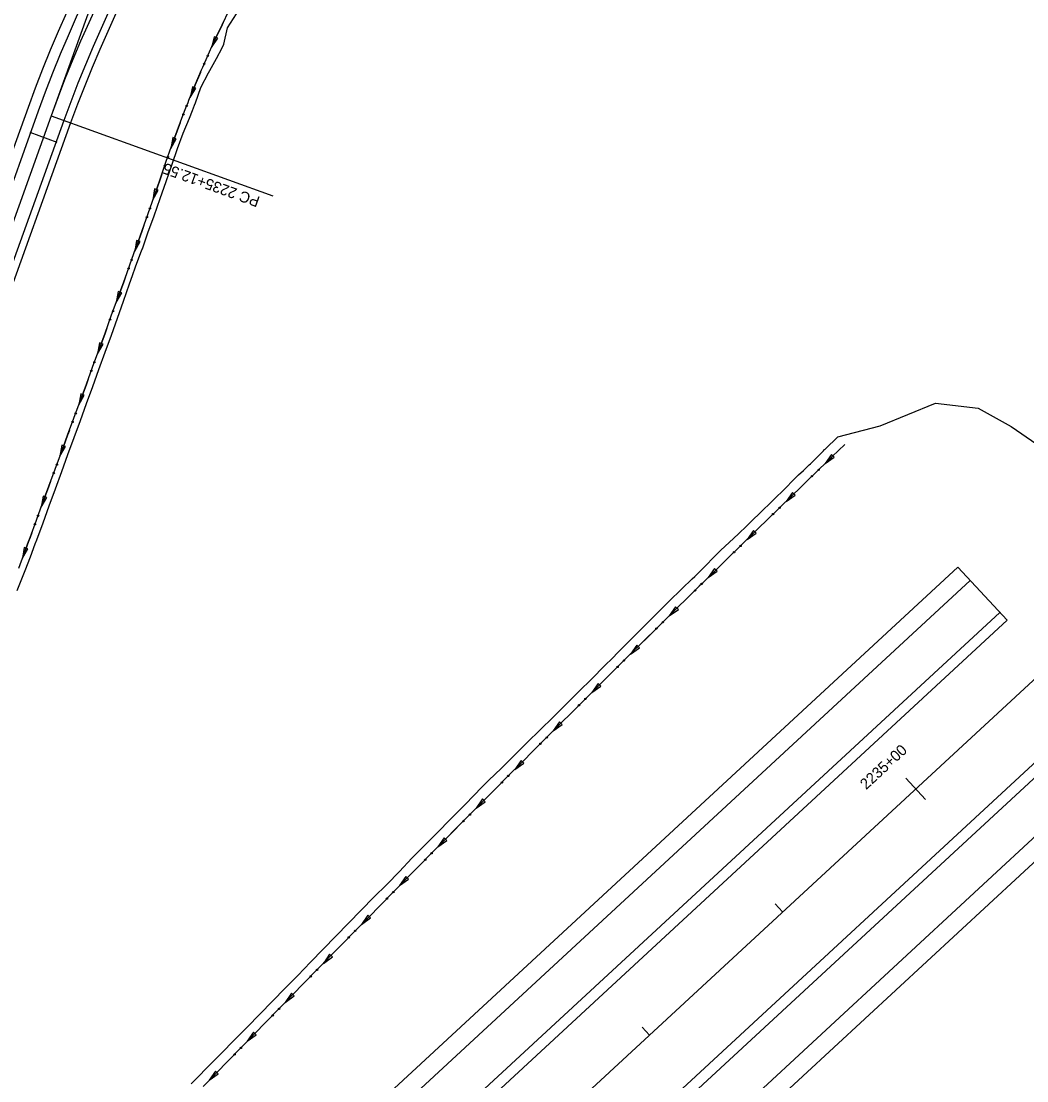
# Model space of a CAD drawing. Extents: x 1611108 to 1749517, y 619561 to 797725.
# Drawn here: x 1727502 to 1728056, y 772043 to 772627 of the extents above; entities that cross this region are included whole.
import ezdxf

# ---------------------------------------------------------------- set-up
doc = ezdxf.new("R2010")
doc.units = 0
for name, color, linetype in [('R_Ditch', 7, 'Continuous'), ('R_Horz Alg', 7, 'Continuous'), ('R_Horz Alg Annot', 7, 'Continuous'), ('R_Horz Alg Stationing', 7, 'Continuous'), ('R_Proposed Const Limits', 7, 'Continuous'), ('R_Proposed Road', 7, 'Continuous')]:
    doc.layers.add(name, color=color, linetype=linetype)

msp = doc.modelspace()

# ---------------------------------------------------------------- linework, layer by layer
at = {"layer": 'R_Ditch'}
for p, q in [((1727608.03, 772618.77), (1727606.46, 772612.89)), ((1727606.46, 772612.89), (1727609.95, 772617.88)), ((1727609.95, 772617.88), (1727608.03, 772618.77)), ((1727595.97, 772591.21), (1727594.68, 772585.26)), ((1727594.68, 772585.26), (1727597.92, 772590.41)), ((1727597.92, 772590.41), (1727595.97, 772591.21)), ((1727585.09, 772563.17), (1727584.03, 772557.17)), ((1727584.03, 772557.17), (1727587.08, 772562.45)), ((1727587.08, 772562.45), (1727585.09, 772563.17)), ((1727575.12, 772534.82), (1727574.14, 772528.81)), ((1727574.14, 772528.81), (1727577.12, 772534.12)), ((1727577.12, 772534.12), (1727575.12, 772534.82)), ((1727565.16, 772506.49), (1727564.16, 772500.48)), ((1727567.15, 772505.78), (1727565.16, 772506.49)), ((1727564.16, 772500.48), (1727567.15, 772505.78)), ((1727555, 772478.23), (1727553.95, 772472.23)), ((1727553.95, 772472.23), (1727556.99, 772477.51)), ((1727556.99, 772477.51), (1727555, 772478.23)), ((1727544.73, 772450.01), (1727543.66, 772444.01)), ((1727543.66, 772444.01), (1727546.71, 772449.28)), ((1727546.71, 772449.28), (1727544.73, 772450.01)), ((1727534.38, 772421.81), (1727533.3, 772415.81)), ((1727533.3, 772415.81), (1727536.36, 772421.08)), ((1727536.36, 772421.08), (1727534.38, 772421.81)), ((1727524.02, 772393.62), (1727522.94, 772387.62)), ((1727522.94, 772387.62), (1727526, 772392.89)), ((1727526, 772392.89), (1727524.02, 772393.62)), ((1727948.41, 772388.44), (1727944.83, 772383.5)), ((1727944.83, 772383.5), (1727949.88, 772386.92)), ((1727949.88, 772386.92), (1727948.41, 772388.44)), ((1727926.84, 772367.52), (1727923.28, 772362.58)), ((1727928.32, 772366.01), (1727926.84, 772367.52)), ((1727513.65, 772365.42), (1727512.58, 772359.42)), ((1727512.58, 772359.42), (1727515.64, 772364.69)), ((1727515.64, 772364.69), (1727513.65, 772365.42)), ((1727923.28, 772362.58), (1727928.32, 772366.01)), ((1727905.32, 772346.56), (1727901.77, 772341.61)), ((1727901.77, 772341.61), (1727906.8, 772345.05)), ((1727906.8, 772345.05), (1727905.32, 772346.56)), ((1727503.29, 772337.23), (1727502.22, 772331.23)), ((1727505.28, 772336.5), (1727503.29, 772337.23)), ((1727502.22, 772331.23), (1727505.28, 772336.5)), ((1727883.85, 772325.56), (1727880.31, 772320.6)), ((1727885.33, 772324.05), (1727883.85, 772325.56)), ((1727880.31, 772320.6), (1727885.33, 772324.05)), ((1727862.42, 772304.5), (1727858.89, 772299.54)), ((1727858.89, 772299.54), (1727863.9, 772303)), ((1727863.9, 772303), (1727862.42, 772304.5)), ((1727841.03, 772283.41), (1727837.52, 772278.43)), ((1727837.52, 772278.43), (1727842.52, 772281.9)), ((1727842.52, 772281.9), (1727841.03, 772283.41)), ((1727819.7, 772262.26), (1727816.19, 772257.28)), ((1727821.19, 772260.76), (1727819.7, 772262.26)), ((1727816.19, 772257.28), (1727821.19, 772260.76)), ((1727798.41, 772241.07), (1727794.91, 772236.08)), ((1727794.91, 772236.08), (1727799.9, 772239.57)), ((1727799.9, 772239.57), (1727798.41, 772241.07)), ((1727777.16, 772219.83), (1727773.67, 772214.84)), ((1727773.67, 772214.84), (1727778.66, 772218.34)), ((1727778.66, 772218.34), (1727777.16, 772219.83)), ((1727755.96, 772198.55), (1727752.48, 772193.55)), ((1727752.48, 772193.55), (1727757.46, 772197.06)), ((1727757.46, 772197.06), (1727755.96, 772198.55)), ((1727734.8, 772177.22), (1727731.34, 772172.21)), ((1727731.34, 772172.21), (1727736.31, 772175.73)), ((1727736.31, 772175.73), (1727734.8, 772177.22)), ((1727713.69, 772155.85), (1727710.24, 772150.83)), ((1727710.24, 772150.83), (1727715.2, 772154.36)), ((1727715.2, 772154.36), (1727713.69, 772155.85)), ((1727692.63, 772134.43), (1727689.19, 772129.4)), ((1727689.19, 772129.4), (1727694.14, 772132.95)), ((1727694.14, 772132.95), (1727692.63, 772134.43)), ((1727671.62, 772112.96), (1727668.18, 772107.93)), ((1727668.18, 772107.93), (1727673.13, 772111.49)), ((1727673.13, 772111.49), (1727671.62, 772112.96)), ((1727650.63, 772091.48), (1727647.19, 772086.45)), ((1727647.19, 772086.45), (1727652.14, 772090)), ((1727652.14, 772090), (1727650.63, 772091.48)), ((1727629.64, 772069.99), (1727626.2, 772064.96)), ((1727626.2, 772064.96), (1727631.15, 772068.51)), ((1727631.15, 772068.51), (1727629.64, 772069.99)), ((1727608.65, 772048.5), (1727605.21, 772043.47)), ((1727605.21, 772043.47), (1727610.16, 772047.02)), ((1727610.16, 772047.02), (1727608.65, 772048.5))]:
    msp.add_line(p, q, dxfattribs=at)
for points in [[(1727500.19, 772325.7), (1727503.01, 772333.39), (1727505.61, 772340.47), (1727505.61, 772340.48), (1727506.46, 772342.78), (1727509.91, 772352.16), (1727513.36, 772361.55), (1727516.81, 772370.93), (1727520.26, 772380.32), (1727523.71, 772389.71), (1727527.16, 772399.09), (1727530.61, 772408.48), (1727534.05, 772417.87), (1727537.5, 772427.25), (1727540.95, 772436.64), (1727544.4, 772446.03), (1727547.83, 772455.42), (1727551.26, 772464.82), (1727554.67, 772474.21), (1727558.07, 772483.62), (1727559.73, 772488.22), (1727561.46, 772493.03), (1727564.85, 772502.44), (1727565.06, 772503.03), (1727568.18, 772511.86), (1727571.5, 772521.3), (1727574.81, 772530.73), (1727578.11, 772540.17), (1727581.4, 772549.62), (1727584.47, 772558.39), (1727587.57, 772566.89), (1727590.77, 772575.36), (1727592.38, 772579.5), (1727593.54, 772582.43), (1727594.08, 772583.78), (1727597.5, 772592.17), (1727601.03, 772600.52), (1727601.67, 772602.02), (1727604.66, 772608.82), (1727607.47, 772615.06), (1727608.41, 772617.07), (1727612.29, 772625.26), (1727616.28, 772633.41)], [(1727612.87, 772626.45), (1727612.29, 772625.26), (1727608.41, 772617.07), (1727607.47, 772615.06), (1727606.49, 772612.87)], [(1727612.89, 772626.48), (1727612.87, 772626.45)], [(1727600.43, 772599.11), (1727597.5, 772592.17), (1727594.68, 772585.26)], [(1727600.45, 772599.15), (1727600.43, 772599.11)], [(1727589.21, 772571.25), (1727587.57, 772566.89), (1727584.47, 772558.39), (1727584.05, 772557.17)], [(1727589.23, 772571.28), (1727589.21, 772571.25)], [(1727579.09, 772542.97), (1727578.11, 772540.17), (1727574.81, 772530.73), (1727574.14, 772528.81)], [(1727579.1, 772543.01), (1727579.09, 772542.97)], [(1727569.15, 772514.62), (1727568.18, 772511.86), (1727565.06, 772503.03), (1727564.85, 772502.44), (1727564.14, 772500.48)], [(1727569.16, 772514.66), (1727569.15, 772514.62)], [(1727559.05, 772486.33), (1727558.07, 772483.62), (1727554.67, 772474.21), (1727553.95, 772472.23)], [(1727559.07, 772486.37), (1727559.05, 772486.33)], [(1727548.81, 772458.1), (1727547.83, 772455.42), (1727544.4, 772446.03), (1727543.66, 772444.01)], [(1727548.82, 772458.13), (1727548.81, 772458.1)], [(1727538.47, 772429.89), (1727537.5, 772427.25), (1727534.05, 772417.87), (1727533.3, 772415.81)], [(1727538.49, 772429.93), (1727538.47, 772429.89)], [(1727528.11, 772401.7), (1727527.16, 772399.09), (1727523.71, 772389.71), (1727522.94, 772387.62)], [(1727528.13, 772401.73), (1727528.11, 772401.7)], [(1727955.61, 772393.93), (1727948.73, 772387.27), (1727948.42, 772386.98), (1727947.74, 772386.31), (1727947.2, 772385.79), (1727945.54, 772384.19), (1727945.27, 772383.93), (1727941.24, 772380.02), (1727940.51, 772379.31), (1727939.85, 772378.67), (1727938.91, 772377.76), (1727936.67, 772375.59), (1727936.67, 772375.59), (1727934.06, 772373.06), (1727930.82, 772369.91), (1727926.88, 772366.08), (1727919.71, 772359.11), (1727912.55, 772352.13), (1727908.52, 772348.2), (1727905.39, 772345.15), (1727900.83, 772340.7), (1727898.23, 772338.15), (1727891.08, 772331.16), (1727890.53, 772330.62), (1727889.65, 772329.76), (1727886.18, 772326.36), (1727883.93, 772324.16), (1727876.79, 772317.15), (1727875.42, 772315.8), (1727869.66, 772310.14), (1727862.52, 772303.12), (1727855.4, 772296.1), (1727850.57, 772291.33), (1727848.28, 772289.07), (1727841.16, 772282.04), (1727840.17, 772281.06), (1727834.05, 772275), (1727831.46, 772272.44), (1727826.94, 772267.96), (1727819.84, 772260.91), (1727812.74, 772253.85), (1727805.65, 772246.79), (1727798.56, 772239.73), (1727791.48, 772232.66), (1727784.4, 772225.58), (1727777.33, 772218.5), (1727770.26, 772211.42), (1727763.2, 772204.33), (1727758.51, 772199.61), (1727756.14, 772197.23), (1727749.09, 772190.13), (1727742.04, 772183.02), (1727734.99, 772175.91), (1727727.96, 772168.79), (1727720.92, 772161.67), (1727713.89, 772154.54), (1727706.87, 772147.41), (1727699.85, 772140.27), (1727692.84, 772133.12), (1727685.83, 772125.97), (1727678.82, 772118.82), (1727671.82, 772111.66), (1727664.83, 772104.5), (1727657.83, 772097.34), (1727650.83, 772090.17), (1727643.83, 772083.01), (1727636.84, 772075.85), (1727629.84, 772068.69), (1727622.84, 772061.52), (1727615.85, 772054.36), (1727608.85, 772047.2), (1727601.85, 772040.04)], [(1727955.61, 772393.93), (1727948.73, 772387.27), (1727948.42, 772386.98), (1727947.74, 772386.31), (1727947.2, 772385.79), (1727945.54, 772384.19), (1727945.27, 772383.93), (1727944.83, 772383.5)], [(1727517.75, 772373.5), (1727516.81, 772370.93), (1727513.36, 772361.55), (1727512.58, 772359.42)], [(1727517.76, 772373.54), (1727517.75, 772373.5)], [(1727934.04, 772373.03), (1727930.82, 772369.91), (1727926.88, 772366.08), (1727923.28, 772362.58)], [(1727934.06, 772373.06), (1727934.06, 772373.06), (1727934.04, 772373.03)], [(1727912.51, 772352.09), (1727908.52, 772348.2), (1727905.39, 772345.15), (1727901.77, 772341.61)], [(1727912.53, 772352.12), (1727912.51, 772352.09)], [(1727507.39, 772345.31), (1727506.46, 772342.78), (1727505.61, 772340.48), (1727505.61, 772340.47), (1727503.01, 772333.39), (1727502.22, 772331.23)], [(1727507.4, 772345.34), (1727507.39, 772345.31)], [(1727891.05, 772331.13), (1727891.02, 772331.1)], [(1727891.02, 772331.1), (1727890.53, 772330.62), (1727889.65, 772329.76), (1727886.18, 772326.36), (1727883.93, 772324.16), (1727880.31, 772320.6)], [(1727869.58, 772310.06), (1727862.52, 772303.12), (1727858.89, 772299.54)], [(1727869.6, 772310.09), (1727869.58, 772310.06)], [(1727848.18, 772288.98), (1727841.16, 772282.04), (1727840.17, 772281.06), (1727837.52, 772278.43)], [(1727848.21, 772289.01), (1727848.18, 772288.98)], [(1727826.83, 772267.85), (1727819.84, 772260.91), (1727816.19, 772257.28)], [(1727826.86, 772267.88), (1727826.83, 772267.85)], [(1727805.53, 772246.67), (1727798.56, 772239.73), (1727794.91, 772236.08)], [(1727805.55, 772246.7), (1727805.53, 772246.67)], [(1727784.27, 772225.45), (1727777.33, 772218.5), (1727773.67, 772214.84)], [(1727784.3, 772225.48), (1727784.27, 772225.45)], [(1727763.06, 772204.19), (1727758.51, 772199.61), (1727756.14, 772197.23), (1727752.48, 772193.55)], [(1727763.08, 772204.21), (1727763.06, 772204.19)], [(1727741.89, 772182.87), (1727734.99, 772175.91), (1727731.34, 772172.21)], [(1727741.92, 772182.9), (1727741.89, 772182.87)], [(1727720.77, 772161.51), (1727713.89, 772154.54), (1727710.24, 772150.83)], [(1727720.8, 772161.54), (1727720.77, 772161.51)], [(1727699.69, 772140.11), (1727692.84, 772133.12), (1727689.19, 772129.4)], [(1727699.72, 772140.14), (1727699.69, 772140.11)], [(1727678.66, 772118.66), (1727671.82, 772111.66), (1727668.18, 772107.93)], [(1727678.69, 772118.69), (1727678.67, 772118.66)], [(1727657.67, 772097.18), (1727650.83, 772090.17), (1727647.19, 772086.45)], [(1727657.7, 772097.2), (1727657.67, 772097.18)], [(1727636.68, 772075.69), (1727629.84, 772068.69), (1727626.2, 772064.96)], [(1727636.71, 772075.72), (1727636.68, 772075.69)], [(1727615.69, 772054.2), (1727608.85, 772047.2), (1727605.21, 772043.47)], [(1727615.72, 772054.23), (1727615.69, 772054.2)]]:
    msp.add_lwpolyline(points, dxfattribs=at)
for centre in [(1727604.47, 772608.29), (1727602.45, 772603.71), (1727592.85, 772580.6), (1727591.03, 772575.93), (1727580.77, 772547.7), (1727582.43, 772552.43), (1727572.51, 772524.07), (1727570.85, 772519.35), (1727562.49, 772495.76), (1727560.79, 772491.05), (1727552.27, 772467.51), (1727550.56, 772462.8), (1727541.97, 772439.3), (1727540.24, 772434.59), (1727531.61, 772411.1), (1727529.88, 772406.4), (1727519.52, 772378.2), (1727521.25, 772382.91), (1727941.26, 772379.99), (1727937.67, 772376.51), (1727510.89, 772354.71), (1727916.13, 772355.57), (1727919.72, 772359.06), (1727509.16, 772350.01), (1727898.22, 772338.09), (1727894.63, 772334.59), (1727873.18, 772313.56), (1727876.76, 772317.07), (1727855.35, 772296), (1727851.78, 772292.48), (1727833.98, 772274.89), (1727830.42, 772271.36), (1727809.11, 772250.19), (1727812.66, 772253.73), (1727791.39, 772232.52), (1727787.85, 772228.98), (1727770.16, 772211.27), (1727766.63, 772207.72), (1727745.45, 772186.41), (1727748.98, 772189.97), (1727727.84, 772168.63), (1727724.32, 772165.06), (1727706.75, 772147.24), (1727703.24, 772143.67), (1727682.2, 772122.22), (1727685.71, 772125.8), (1727664.71, 772104.33), (1727661.21, 772100.74), (1727643.72, 772082.84), (1727640.22, 772079.26), (1727619.23, 772057.77), (1727622.73, 772061.35)]:
    msp.add_circle(centre, 0.375, dxfattribs=at)
at = {"layer": 'R_Horz Alg'}
for p, q in [((1726122.78, 770473.69), (1737235.67, 780746.34)), ((1727518.02, 772575.19), (1727287.33, 771935.59))]:
    msp.add_line(p, q, dxfattribs=at)
msp.add_arc((1728191.74, 772332.19), 716.2, 104.4, 160.16667, dxfattribs=at)
at = {"layer": 'R_Horz Alg Annot'}
for points in [[(1728013.62, 773025.89), (1727646.59, 772931.65), (1727518.02, 772575.19)], [(1727518.02, 772575.19), (1727640.31, 772531.08)]]:
    msp.add_lwpolyline(points, dxfattribs=at)
at = {"layer": 'R_Horz Alg Stationing'}
for points in [[(1727506.24, 772566.1), (1727521.29, 772560.67)], [(1727989.4, 772210.07), (1728000.26, 772198.32)], [(1727917.32, 772140.72), (1727921.4, 772136.31)], [(1727843.89, 772072.84), (1727847.96, 772068.43)]]:
    msp.add_lwpolyline(points, dxfattribs=at)
at = {"layer": 'R_Proposed Const Limits'}
for points in [[(1727499.42, 772313.42), (1727503.06, 772322.74), (1727503.71, 772324.42), (1727503.71, 772324.43), (1727506.66, 772332.07), (1727509.35, 772339.12), (1727509.35, 772339.13), (1727510.23, 772341.42), (1727513.62, 772350.82), (1727517.06, 772360.21), (1727520.52, 772369.59), (1727523.96, 772378.99), (1727527.37, 772388.38), (1727530.79, 772397.78), (1727534.23, 772407.17), (1727537.63, 772416.58), (1727541, 772425.99), (1727544.42, 772435.39), (1727547.9, 772444.77), (1727551.33, 772454.16), (1727554.74, 772463.56), (1727558.05, 772473), (1727561.35, 772482.44), (1727562.97, 772487.05), (1727564.66, 772491.87), (1727568.14, 772501.25), (1727568.36, 772501.84), (1727571.47, 772510.68), (1727574.83, 772520.1), (1727578.15, 772529.53), (1727581.45, 772538.97), (1727584.74, 772548.41), (1727587.81, 772557.14), (1727590.94, 772565.58), (1727594.38, 772573.9), (1727595.98, 772578.02), (1727597.1, 772580.94), (1727597.62, 772582.3), (1727600.7, 772590.77), (1727604.75, 772598.83), (1727605.64, 772600.21), (1727609.23, 772606.66), (1727612.32, 772612.71), (1727613.34, 772614.66), (1727615.39, 772623.7), (1727620.2, 772631.36)], [(1727975.2, 772404.26), (1728005.73, 772416.83), (1728029.28, 772414.02), (1728047.45, 772403.84), (1728061.62, 772394.06), (1728075.84, 772379.85), (1728176.79, 772271.62), (1728196.21, 772249.33), (1728201.8, 772239.35), (1728206.79, 772219.99), (1728207, 772200.23), (1728202.16, 772184.59)], [(1727595.26, 772041.53), (1727597.95, 772044.25), (1727604.98, 772051.38), (1727612.01, 772058.51), (1727619.04, 772065.64), (1727626.07, 772072.77), (1727633.08, 772079.91), (1727640.1, 772087.05), (1727647.11, 772094.2), (1727654.13, 772101.33), (1727661.1, 772108.53), (1727668.07, 772115.72), (1727675.06, 772122.89), (1727682.08, 772130.03), (1727689.08, 772137.19), (1727696.09, 772144.34), (1727703.1, 772151.49), (1727710.11, 772158.63), (1727717.04, 772165.87), (1727724.04, 772173.03), (1727731.09, 772180.14), (1727738.15, 772187.23), (1727745.21, 772194.33), (1727752.17, 772201.53), (1727754.51, 772203.95), (1727759.18, 772208.67), (1727766.4, 772215.59), (1727773.5, 772222.64), (1727780.63, 772229.66), (1727787.75, 772236.69), (1727794.85, 772243.74), (1727801.98, 772250.77), (1727809.09, 772257.8), (1727816.17, 772264.87), (1727823.25, 772271.95), (1727827.75, 772276.45), (1727830.31, 772279.04), (1727836.38, 772285.15), (1727837.36, 772286.14), (1727844.43, 772293.23), (1727846.7, 772295.51), (1727851.5, 772300.32), (1727858.59, 772307.37), (1727865.78, 772314.33), (1727871.59, 772319.94), (1727872.98, 772321.28), (1727880.08, 772328.32), (1727882.27, 772330.58), (1727885.66, 772334.07), (1727886.52, 772334.95), (1727887.07, 772335.49), (1727894.43, 772342.26), (1727897.06, 772344.78), (1727901.64, 772349.2), (1727904.78, 772352.24), (1727908.83, 772356.15), (1727916.03, 772363.09), (1727923.17, 772370.1), (1727926.97, 772374.08), (1727930.22, 772377.21), (1727932.92, 772379.65), (1727935.18, 772381.81), (1727936.1, 772382.73), (1727936.76, 772383.38), (1727937.48, 772384.09), (1727941.46, 772388.05), (1727941.73, 772388.32), (1727943.36, 772389.94), (1727943.9, 772390.47), (1727944.57, 772391.14), (1727944.87, 772391.44), (1727951.76, 772398.1), (1727975.2, 772404.26)]]:
    msp.add_lwpolyline(points, dxfattribs=at)
at = {"layer": 'R_Proposed Road'}
for p, q in [((1727505.32, 772579.77), (1727274.63, 771940.17)), ((1727510.97, 772577.73), (1727280.28, 771938.14)), ((1727525.08, 772572.64), (1727294.39, 771933.05)), ((1727528.84, 772571.29), (1727298.15, 771931.69)), ((1726991.58, 771377.57), (1728018.03, 772326.41)), ((1728045.18, 772297.04), (1728018.03, 772326.41)), ((1726910.49, 771288.99), (1728024.82, 772319.07)), ((1726095.63, 770503.06), (1728041.11, 772301.44)), ((1726099.71, 770498.66), (1728045.18, 772297.04)), ((1726145.86, 770448.72), (1728091.34, 772247.1)), ((1726149.94, 770444.32), (1728095.41, 772242.7)), ((1727151.11, 771337.11), (1728111.7, 772225.07)), ((1727157.9, 771329.77), (1728118.49, 772217.73))]:
    msp.add_line(p, q, dxfattribs=at)
for radius in [729.7, 723.7, 708.7, 704.7]:
    msp.add_arc((1728191.74, 772332.19), radius, 104.4, 160.16667, dxfattribs=at)

# ---------------------------------------------------------------- texts
at = {"layer": 'R_Horz Alg Annot'}
msp.add_text('PC 2235+12.55', height=6, rotation=160.16667, dxfattribs=at).set_placement((1727633.65, 772530.29))
at = {"layer": 'R_Horz Alg Stationing'}
msp.add_text('2235+00', height=6, rotation=42.75, dxfattribs=at).set_placement((1727967.45, 772203.39))

doc.saveas('drawing.dxf')
